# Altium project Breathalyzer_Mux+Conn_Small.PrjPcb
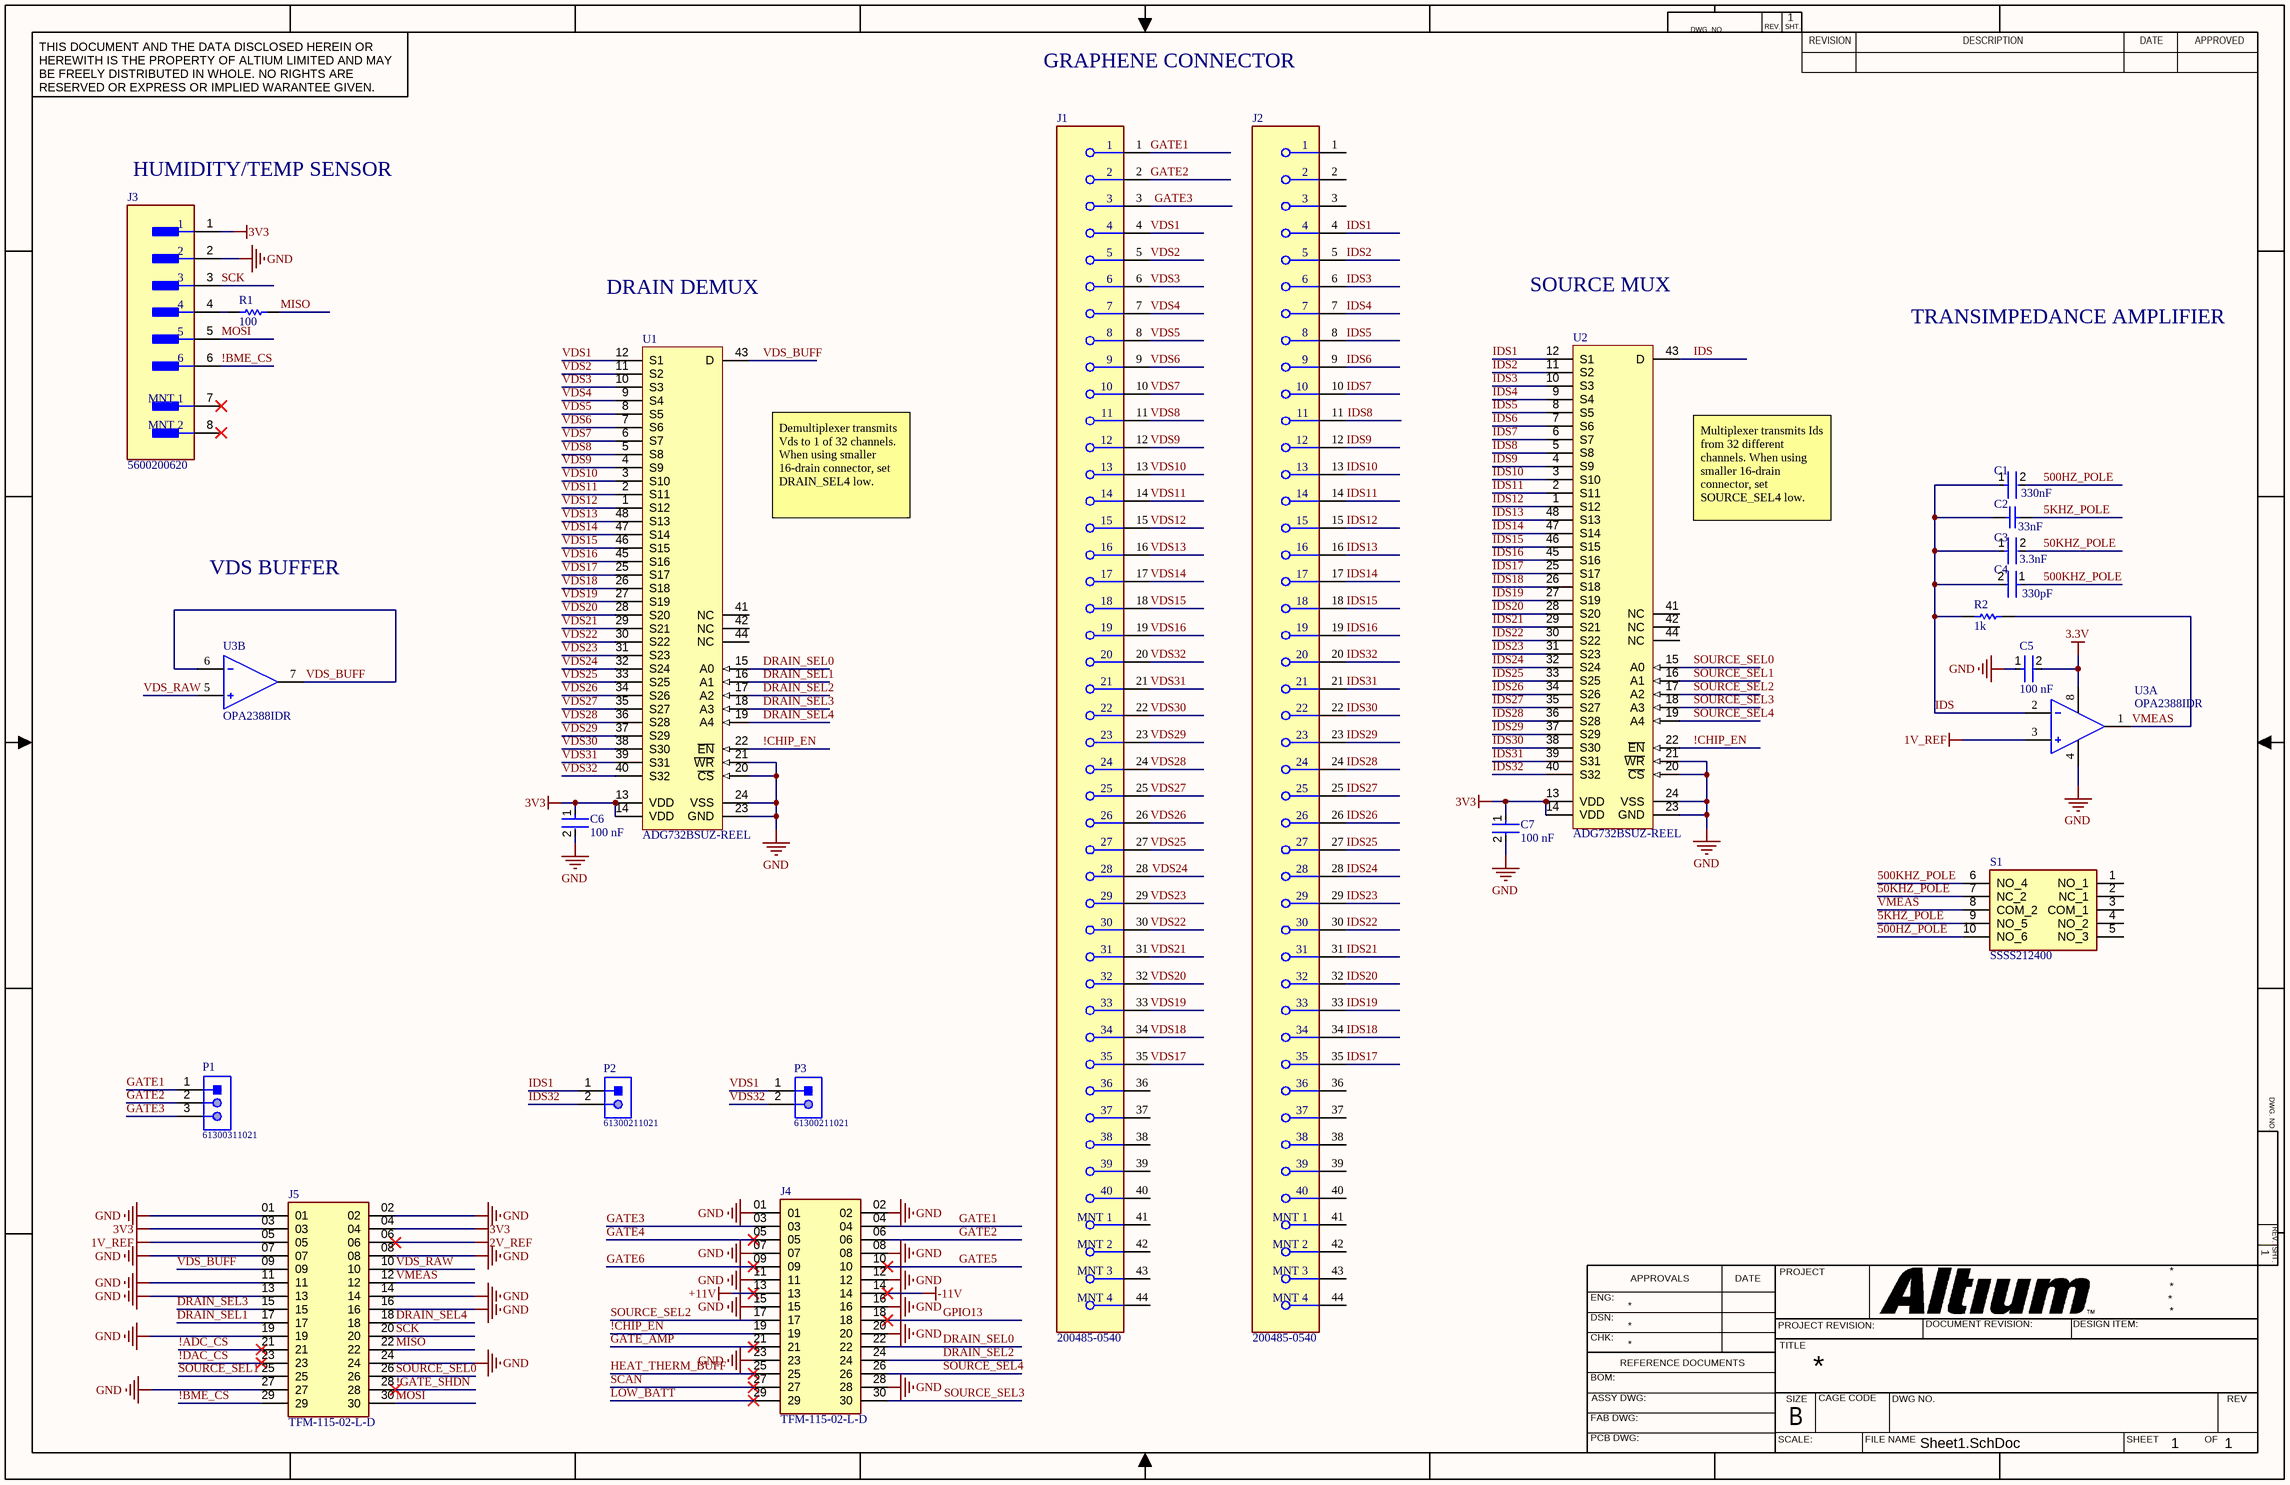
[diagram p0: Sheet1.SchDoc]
1 sheet, 21 parts. Net scope: global (net labels, ports and power ports of the same name join across sheets).
Board file: PCB1.PcbDoc

## Sheet Sheet1.SchDoc
size 431 x 279 mm; SheetNumber: 1; SheetTotal: 1

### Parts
C1  330nF  [FP-CC0805-0_85-MFG]
C2  33nF  [CAPC2013X95X45NL10T25]
C3  3.3nF  [FP-C0805C-DN-MFG]
C4  330pF  [FP-C0805C-DN-MFG]
C5  100 nF  [FP-C0805C-DN-MFG]
C6  100 nF  [FP-C0805C-DN-MFG]
C7  100 nF  [FP-C0805C-DN-MFG]
J1  200485-0540  [FP-200485-0540-MFG]
J2  200485-0540  [FP-200485-0540-MFG]
J3  5600200620  [FP-5600200620-MFG]
J4  TFM-115-02-L-D  [SAMTEC_TFM-115-02-L-D]
J5  TFM-115-02-L-D  [SAMTEC_TFM-115-02-L-D]
P1  61300311021  [61300311021]
P2  61300211021  [61300211021]
P3  61300211021  [61300211021]
R1  100  [RESC2013X50X30LL20T20]
R2  1k  [RESC2013X55X40LL15T20]
S1  SSSS212400  [SSSS212400]
U1  ADG732BSUZ-REEL  [ADI-SU-48_N]
U2  ADG732BSUZ-REEL  [ADI-SU-48_N]
U3  OPA2388IDR  [FP-D0008A-IPC_B]  (parts A,B of 2)

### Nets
1V_REF: J5.05 U3.3(+IN_A)
2V_REF: J5.06
3.3V: C5.2 U3.8(V+)
3V3: C6.1 C7.1 J3.1 J5.03 J5.04 U1.13(VDD) U1.14(VDD) U2.13(VDD) U2.14(VDD)
+11V: J4.13
-11V: J4.14
GND: C5.1 C6.2 C7.2 J3.2 J4.01 J4.02 J4.07 J4.08 J4.11 J4.12 J4.15 J4.16 J4.20 J4.23 J4.28 J5.01 J5.02 J5.07 J5.08 J5.11 J5.13 J5.14 J5.16 J5.19 J5.24 J5.27 U1.20(~{CS}) U1.21(~{WR}) U1.23(GND) U1.24(VSS) U2.20(~{CS}) U2.21(~{WR}) U2.23(GND) U2.24(VSS) U3.4(V-)
5KHZ_POLE: C2.2 S1.9(NO_5)
50KHZ_POLE: C3.2 S1.7(NC_2)
500HZ_POLE: C1.2 S1.10(NO_6)
500KHZ_POLE: C4.1 S1.6(NO_4)
!ADC_CS: J5.21
!BME_CS: J3.6 J5.29
!CHIP_EN: J4.19 U1.22(~{EN}) U2.22(~{EN})
!DAC_CS: J5.23
!GATE_SHDN: J5.28
DRAIN_SEL0: J4.22 U1.15(A0)
DRAIN_SEL1: J5.17 U1.16(A1)
DRAIN_SEL2: J4.24 U1.17(A2)
DRAIN_SEL3: J5.15 U1.18(A3)
DRAIN_SEL4: J5.18 U1.19(A4)
GATE1: J1.1 J4.04 P1.1
GATE2: J1.2 J4.06 P1.2
GATE3: J1.3 J4.03 P1.3
GATE4: J4.05
GATE5: J4.10
GATE6: J4.09
GATE_AMP: J4.21
GPIO13: J4.18
HEAT_THERM_BUFF: J4.25
IDS: C1.1 C2.1 C3.1 C4.2 R2.1 U2.43(D) U3.2(-IN_A)
IDS1: J2.4 P2.1 U2.12(S1)
IDS2: J2.5 U2.11(S2)
IDS3: J2.6 U2.10(S3)
IDS4: J2.7 U2.9(S4)
IDS5: J2.8 U2.8(S5)
IDS6: J2.9 U2.7(S6)
IDS7: J2.10 U2.6(S7)
IDS8: J2.11 U2.5(S8)
IDS9: J2.12 U2.4(S9)
IDS10: J2.13 U2.3(S10)
IDS11: J2.14 U2.2(S11)
IDS12: J2.15 U2.1(S12)
IDS13: J2.16 U2.48(S13)
IDS14: J2.17 U2.47(S14)
IDS15: J2.18 U2.46(S15)
IDS16: J2.19 U2.45(S16)
IDS17: J2.35 U2.25(S17)
IDS18: J2.34 U2.26(S18)
IDS19: J2.33 U2.27(S19)
IDS20: J2.32 U2.28(S20)
IDS21: J2.31 U2.29(S21)
IDS22: J2.30 U2.30(S22)
IDS23: J2.29 U2.31(S23)
IDS24: J2.28 U2.32(S24)
IDS25: J2.27 U2.33(S25)
IDS26: J2.26 U2.34(S26)
IDS27: J2.25 U2.35(S27)
IDS28: J2.24 U2.36(S28)
IDS29: J2.23 U2.37(S29)
IDS30: J2.22 U2.38(S30)
IDS31: J2.21 U2.39(S31)
IDS32: J2.20 P2.2 U2.40(S32)
LOW_BATT: J4.29
MISO: J5.22 R1.2
MOSI: J3.5 J5.30
SCAN: J4.27
SCK: J3.3 J5.20
SOURCE_SEL0: J5.26 U2.15(A0)
SOURCE_SEL1: J5.25 U2.16(A1)
SOURCE_SEL2: J4.17 U2.17(A2)
SOURCE_SEL3: J4.30 U2.18(A3)
SOURCE_SEL4: J4.26 U2.19(A4)
VDS1: J1.4 P3.1 U1.12(S1)
VDS2: J1.5 U1.11(S2)
VDS3: J1.6 U1.10(S3)
VDS4: J1.7 U1.9(S4)
VDS5: J1.8 U1.8(S5)
VDS6: J1.9 U1.7(S6)
VDS7: J1.10 U1.6(S7)
VDS8: J1.11 U1.5(S8)
VDS9: J1.12 U1.4(S9)
VDS10: J1.13 U1.3(S10)
VDS11: J1.14 U1.2(S11)
VDS12: J1.15 U1.1(S12)
VDS13: J1.16 U1.48(S13)
VDS14: J1.17 U1.47(S14)
VDS15: J1.18 U1.46(S15)
VDS16: J1.19 U1.45(S16)
VDS17: J1.35 U1.25(S17)
VDS18: J1.34 U1.26(S18)
VDS19: J1.33 U1.27(S19)
VDS20: J1.32 U1.28(S20)
VDS21: J1.31 U1.29(S21)
VDS22: J1.30 U1.30(S22)
VDS23: J1.29 U1.31(S23)
VDS24: J1.28 U1.32(S24)
VDS25: J1.27 U1.33(S25)
VDS26: J1.26 U1.34(S26)
VDS27: J1.25 U1.35(S27)
VDS28: J1.24 U1.36(S28)
VDS29: J1.23 U1.37(S29)
VDS30: J1.22 U1.38(S30)
VDS31: J1.21 U1.39(S31)
VDS32: J1.20 P3.2 U1.40(S32)
VDS_BUFF: J5.09 U1.43(D) U3.6(-IN_B) U3.7(OUT_B)
VDS_RAW: J5.10 U3.5(+IN_B)
VMEAS: J5.12 R2.2 S1.8(COM_2) U3.1(OUT_A)
NetJ3_4: J3.4 R1.1

Not connected (* = marked no-connect by the designer): J1 36 37 38 39 40 41(MNT_1) 42(MNT_2) 43(MNT_3) 44(MNT_4); J2 1 2 3 36 37 38 39 40 41(MNT_1) 42(MNT_2) 43(MNT_3) 44(MNT_4); J3 7(MNT_1)* 8(MNT_2)*; S1 1(NO_1) 2(NC_1) 3(COM_1) 4(NO_2) 5(NO_3); U1 41(NC) 42(NC) 44(NC); U2 41(NC) 42(NC) 44(NC)

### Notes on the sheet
- GRAPHENE CONNECTOR
- (near J3) HUMIDITY/TEMP SENSOR
- DRAIN DEMUX
- SOURCE MUX
- TRANSIMPEDANCE AMPLIFIER
- (near U1) Demultiplexer transmits Vds to 1 of 32 channels. When using smaller 16-drain connector, set DRAIN_SEL4 low.
- (near U2) Multiplexer transmits Ids from 32 different channels. When using smaller 16-drain connector, set SOURCE_SEL4 low.
- VDS BUFFER

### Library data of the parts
C1 = CMP-03422-000882-1: Surface Mount Ceramic Multilayer Capacitor 0.33uF 10% X7R 16V 0805 Blister T/R; Manufacturer Part Number: CC0805KKX7R7BB334; Manufacturer: Yageo; Tolerance: 0.1
C2 = CMP-1036-04169-2: Manufacturer: Murata; Part Number: GRM219R71H333KA01D
C3 = CMP-2007-00373-2: CAP CER 3300PF 50V X7R 0805; Manufacturer: KEMET; Manufacturer Part Number: C0805C332K5RACTU; Capacitance: 3,300 pF; Tolerance: 0.1; Material: Ceramic; Temperature Coefficient: 30ppm/°C; Value: 3,300 pF
C4 = CMP-2007-00598-2: CAP CER 330PF 50V C0G/NP0 0805; Manufacturer: KEMET; Manufacturer Part Number: C0805C331J5GACTU; Temperature Coefficient: 30ppm/°C; Tolerance: 0.05; Temperature Characteristic: C0G; Material: Ceramic
C5-C7 = CMP-2007-00279-2: CAP CER 0.1UF 50V X7R 0805; Manufacturer Part Number: C0805C104K5RACTU; Manufacturer: KEMET; Value: 0.10 μF; Tolerance: 0.1; Temperature Coefficient: 30ppm/°C; Material: Ceramic
J1 J2 = CMP-04775-000016-1: 0.5ONE-TOUCH ST 40P
J3 = CMP-04776-000066-1: CONN HEADER SMD 6POS 2MM; Manufacturer: Molex; Conn Gender: Male; Conn Orientation: Vertical; Current Rating: 3A; Number Of Contacts: 6; Voltage Rating: 125V
J4 J5 = TFM-115-02-L-D: MF: Samtec Inc.; System: Connector
P1 = CMP-1502-01061-1: THT Angled Pin Header WR-PHD, Pitch 2.54 mm, Single Row, 3 pins; Manufacturer: Wurth Elektronik; Pitch: 2.54mm; Contact Resistance: 20mOhm; Gender: Male; Pin Number: 3; Rated Current: 3A; Working Voltage: 250VAC; Withstanding Voltage: 500VAC
P2 P3 = CMP-1502-01059-1: THT Angled Pin Header WR-PHD, Pitch 2.54 mm, Single Row, 2 pins; Manufacturer: Wurth Elektronik; Withstanding Voltage: 500VAC; Gender: Male; Pitch: 2.54mm; Pin Number: 2; Rated Current: 3A; Contact Resistance: 20mOhm; Working Voltage: 250VAC
R1 = CMP-2001-04901-1: Manufacturer: Vishay Dale; Part Number: CRCW0805100RFKEA
R2 = CMP-2001-04738-1: TNPW08051K00BEEN; Manufacturer: Vishay Dale
S1 = SSSS212400: Switch; Manufacturer_Name: ALPS Electric
U1 U2 = CMP-0798-00236-1: 1.8 to 5.5 V / +/-2.5 V, 4 Ohm, 32-Channel Analog Multiplexer, -40 to 85 degC, 48-pin QFP (SU-48), Reel; Manufacturer: Analog Devices; Ron (ohms): 4; Max Analog Signal Range: Vss to Vdd; Bandwidth (Hz): 18M; Supply V Guar Performance: Dual_(+/-2.5V), Single_(+3V), Single_(+5V); t transition (s): 23n
U3 = CMP-04895-000483-1: IC OPAMP ZER-DRIFT 2CIRC 8SOIC; Number of Channels: 2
